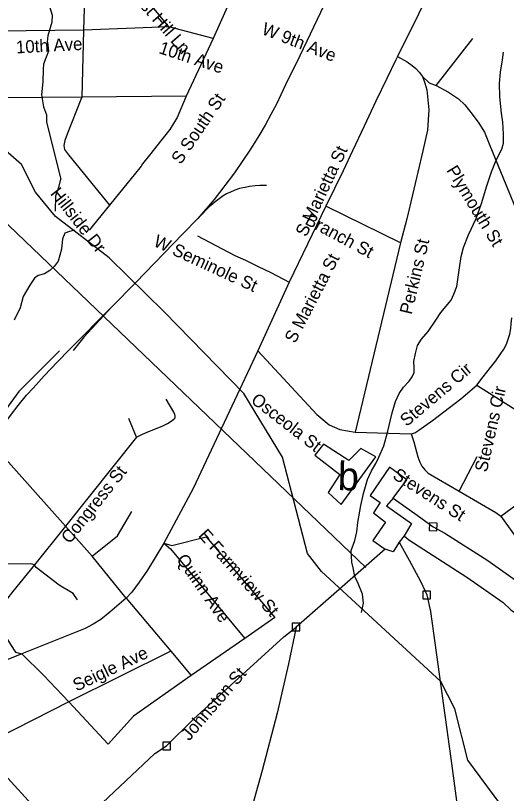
# Model space of a CAD drawing. Extents: x 1268485 to 1426702, y 514839 to 616766.
# Drawn here: x 1346750 to 1349305, y 549246 to 553298 of the extents above; entities that cross this region are included whole.
import ezdxf

# ---------------------------------------------------------------- set-up
doc = ezdxf.new("R2010")
doc.units = 0
for name, color, linetype in [('Old_Level_10', 7, 'Continuous'), ('Old_Level_22', 7, 'Continuous'), ('Old_Level_35', 7, 'Continuous'), ('Old_Level_44', 7, 'Continuous'), ('Old_Level_56', 7, 'Continuous'), ('Old_Level_59', 7, 'Continuous'), ('Old_Level_62', 7, 'Continuous')]:
    doc.layers.add(name, color=color, linetype=linetype)

msp = doc.modelspace()

# ---------------------------------------------------------------- linework, layer by layer
at = {"layer": 'Old_Level_35'}
for p, q in [((1347114.473, 553585.416), (1347104.016, 553222.422)), ((1347916.329, 553491.143), (1347778.534, 553178.797)), ((1347547.953, 553239.185), (1347104.016, 553222.422)), ((1347778.534, 553178.797), (1347547.953, 553239.185)), ((1347104.016, 553222.422), (1346625.116, 553216.68)), ((1347104.016, 553222.422), (1347093.968, 552872.603)), ((1347778.534, 553178.797), (1347637.766, 552877.986)), ((1348939.232, 552934.016), (1349129.828, 553178.9)), ((1347637.766, 552877.986), (1347093.968, 552872.603)), ((1347238.53, 552309.684), (1347132.62, 552180.399)), ((1348365.086, 552305.634), (1348173.772, 551908.961)), ((1348753.044, 552114.73), (1348365.086, 552305.634)), ((1348753.044, 552114.73), (1348517.952, 551127.712)), ((1348173.772, 551908.961), (1348010.756, 551551.914)), ((1349151.666, 551373.211), (1349714.226, 551015.549)), ((1347379.913, 551101.26), (1347339.108, 551198.814)), ((1347009.589, 550637.33), (1346596.512, 551101.363)), ((1347378.99, 551101.927), (1347009.589, 550637.33)), ((1348517.952, 551127.712), (1348809.844, 551118.587)), ((1349275.415, 550690.08), (1349714.226, 551015.549)), ((1349059.597, 550821.211), (1349152.999, 551001.452)), ((1347009.589, 550637.33), (1346847.598, 550436.123)), ((1347147.897, 550481.696), (1347009.589, 550637.33)), ((1347324.857, 550262.29), (1347147.897, 550481.696)), ((1347324.857, 550262.29), (1347557.796, 549987.52)), ((1348099.133, 550163.147), (1347942.474, 550052.266)), ((1347942.474, 550052.266), (1347664.423, 549859.875)), ((1347557.796, 549987.52), (1347027.224, 549722.132)), ((1347557.796, 549987.52), (1347664.423, 549859.875)), ((1347027.224, 549722.132), (1346562.165, 549485.86)), ((1347231.25, 549501.547), (1347027.224, 549722.132)), ((1346562.165, 549485.86), (1347055.008, 548948.931))]:
    msp.add_line(p, q, dxfattribs=at)
for points in [[(1347547.953, 553239.185), (1347271.031, 553581.263), (1347114.473, 553585.416)], [(1348956.046, 553527.078), (1348847.163, 553305.673), (1348738.383, 553084.319)], [(1348738.383, 553084.319), (1348730.284, 553068.018), (1348683.122, 552970.515), (1348626.015, 552851.944), (1348563.884, 552721.634), (1348503.496, 552593.732), (1348454.489, 552488.745), (1348365.086, 552305.634)], [(1348738.383, 553084.319), (1348788.724, 553057.201), (1348814.253, 553038.08), (1348833.425, 553022.138), (1348850.342, 553004.041), (1348868.489, 552981.23)], [(1348868.489, 552981.23), (1348880.279, 552946.832), (1348890.327, 552910.743), (1348900.579, 552806.525), (1348894.223, 552700.923), (1348870.744, 552594.194), (1348843.472, 552482.081), (1348815.483, 552363.51), (1348787.596, 552239.915), (1348753.044, 552114.73)], [(1348868.489, 552981.23), (1348903.04, 552947.755), (1348939.232, 552934.016)], [(1348939.232, 552934.016), (1349002.9, 552899.927), (1349055.906, 552864.913), (1349088.1, 552832.618), (1349127.675, 552784.175), (1349160.791, 552737.576), (1349191.241, 552690.004), (1349218.615, 552621.312), (1349425.205, 552117.14)], [(1347093.968, 552872.603), (1346689.298, 552869.117), (1346664.076, 552870.194), (1346649.108, 552872.705), (1346638.342, 552878.754)], [(1347093.968, 552872.603), (1347088.637, 552861.582), (1347017.996, 552680.828), (1347005.488, 552646.687), (1347001.387, 552620.953), (1347004.77, 552600.14), (1347024.66, 552572.612), (1347238.53, 552309.684)], [(1347637.766, 552877.986), (1347591.014, 552767.976), (1347552.67, 552704.512), (1347504.995, 552644.124), (1347454.757, 552580.301), (1347410.671, 552525.194)], [(1347410.671, 552525.194), (1347403.494, 552513.352), (1347366.79, 552468.805), (1347313.476, 552401.752), (1347238.53, 552309.684)], [(1347696.924, 552151.332), (1347891.211, 552048.243), (1347946.985, 552024.252), (1348013.011, 551991.289), (1348078.116, 551960.275), (1348173.772, 551908.961)], [(1349301.251, 551576.264), (1349306.583, 551591.438), (1349314.887, 551612.558), (1349322.269, 551638.087), (1349327.6, 551668.024), (1349330.676, 551692.99), (1349333.137, 551724.363)], [(1349151.666, 551373.211), (1349184.987, 551415.4), (1349222.204, 551464.459), (1349249.27, 551499.267), (1349273.262, 551532.127), (1349290.896, 551560.577), (1349301.251, 551576.264)], [(1346977.909, 551550.991), (1346765.987, 551339.583), (1346711.238, 551262.791), (1346596.512, 551101.363)], [(1348010.756, 551551.914), (1347673.548, 550834.129), (1347521.502, 550549.517)], [(1348010.756, 551551.914), (1348318.744, 551219.422), (1348382.72, 551166.877), (1348438.392, 551141.81), (1348517.952, 551127.712)], [(1348809.844, 551118.587), (1348827.786, 551124.073), (1348844.6, 551135.504), (1348921.085, 551189.074), (1349067.082, 551301.956), (1349151.666, 551373.211)], [(1347379.913, 551101.26), (1347410.979, 551117.101), (1347447.785, 551132.378), (1347512.377, 551159.29), (1347540.469, 551173.491), (1347564.46, 551188.92), (1347576.148, 551197.327), (1347580.147, 551202.761), (1347580.659, 551206.914), (1347580.659, 551210.707), (1347579.634, 551219.627), (1347574.405, 551232.084), (1347533.907, 551299.443)], [(1348809.844, 551118.587), (1348823.582, 551077.372), (1348843.267, 550999.606), (1348853.725, 550972.18), (1348865.208, 550951.572), (1348880.279, 550931.939), (1348898.426, 550913.638), (1349059.597, 550821.211)], [(1349059.597, 550821.211), (1349250.398, 550710.073), (1349275.415, 550690.08)], [(1347147.897, 550481.696), (1347279.745, 550587.862), (1347355.615, 550714.43)], [(1349275.415, 550690.08), (1349483.235, 550401.213), (1349557.156, 550332.11), (1349627.489, 550291.612), (1349677.624, 550265.776)], [(1347521.502, 550549.517), (1347562.922, 550537.265), (1347742.65, 550581.915), (1348099.133, 550163.147)], [(1347521.502, 550549.517), (1347437.225, 550409.415), (1347393.139, 550346.874), (1347354.384, 550294.125), (1347324.857, 550262.29)], [(1347521.502, 550549.517), (1347555.848, 550519.835), (1347942.474, 550052.266)], [(1346847.598, 550436.123), (1346829.963, 550441.916), (1346447.029, 550438.379), (1346386.231, 550438.635), (1346358.036, 550437.302), (1346339.581, 550436.328), (1346321.639, 550432.637), (1346304.005, 550426.947), (1346283.91, 550418.232)], [(1346847.598, 550436.123), (1346733.897, 550296.636), (1346704.369, 550257.676), (1346690.426, 550229.738), (1346678.533, 550187.087)], [(1347071.72, 550255.062), (1347049.164, 550286.948), (1346977.088, 550331.187), (1346856.415, 550422.641), (1346847.598, 550436.123)], [(1347324.857, 550262.29), (1347241.093, 550190.317), (1347193.111, 550152.382), (1347153.536, 550128.391), (1347111.603, 550105.477), (1346782.391, 549973.269)], [(1346678.533, 550187.087), (1346676.79, 550168.684), (1346678.533, 550151.254), (1346683.044, 550123.111), (1346689.708, 550096.762), (1346697.602, 550070.31), (1346707.137, 550047.857), (1346722.926, 550022.021), (1346749.275, 549982.138), (1346782.391, 549973.269)], [(1346782.391, 549973.269), (1346550.888, 549881.816), (1346491.217, 549852.698), (1346439.544, 549817.789), (1346344.503, 549735.819)], [(1347027.224, 549722.132), (1346895.58, 549862.438), (1346782.391, 549973.269)], [(1347664.423, 549859.875), (1347362.996, 549648.979), (1347231.25, 549501.547)]]:
    msp.add_lwpolyline(points, dxfattribs=at)
at = {"layer": 'Old_Level_44'}
for points in [[(1348444.749, 553541.38), (1348229.239, 553088.83), (1348155.83, 552937.707), (1348131.224, 552885.521), (1348107.335, 552837.078), (1348079.038, 552783.2), (1348048.485, 552727.273), (1348021.419, 552680.059), (1348002.246, 552649.199), (1347969.951, 552597.013), (1347890.288, 552479.672), (1347783.046, 552340.237), (1347697.846, 552240.889)], [(1347697.846, 552240.889), (1347765.001, 552308.505), (1347789.3, 552329.369), (1347808.882, 552344.44), (1347831.335, 552360.69), (1347848.457, 552370.687), (1347867.425, 552379.043), (1347893.261, 552389.962), (1347917.457, 552398.677), (1347932.529, 552402.88), (1347945.857, 552404.931), (1347967.49, 552409.544), (1347996.71, 552413.338), (1348022.239, 552415.388), (1348041.411, 552414.927), (1348055.97, 552415.388)], [(1347251.551, 551781.213), (1347375.094, 551908.243), (1347620.952, 552161.124), (1347697.846, 552240.889)], [(1345456.73, 549157.674), (1345521.834, 549285.422), (1345542.339, 549321.768), (1345574.019, 549373.492), (1345788.299, 549725.053), (1345901.385, 549906.679), (1345943.523, 549975.935), (1345968.642, 550014.382), (1346066.247, 550172.99), (1346066.76, 550172.99), (1346186.51, 550370.507), (1346285.55, 550530.395), (1346354.345, 550639.381), (1346410.222, 550730.373), (1346617.324, 551065.171), (1346675.354, 551147.859), (1346722.619, 551213.834), (1346763.527, 551266.892), (1346806.895, 551319.898), (1346840.729, 551357.422), (1346897.836, 551421.296), (1346968.476, 551494.397), (1347031.12, 551558.271), (1347251.551, 551781.213)], [(1347251.551, 551781.213), (1347105.041, 551623.375), (1347050.292, 551552.837)]]:
    msp.add_lwpolyline(points, dxfattribs=at)
at = {"layer": 'Old_Level_56'}
for p, q in [((1348772.91, 550588.239), (1348746.228, 550554.96)), ((1348673.258, 550518.411), (1348210.069, 550112.54))]:
    msp.add_line(p, q, dxfattribs=at)
for points in [[(1343197.859, 555401.572), (1343694.839, 555209.776), (1344145.672, 555017.979), (1344450.24, 554823.724), (1344690.819, 554583.044), (1345107.207, 554064.657), (1346134.297, 552759.432), (1348573.366, 550422.633)], [(1348437.788, 550907.937), (1348377.651, 550813.102), (1348444.243, 550751.533), (1348625.926, 550999.795), (1348546.771, 551043.609), (1348485.478, 550980.813), (1348353.125, 551065.718), (1348307.958, 551008.799), (1348437.788, 550907.937)], [(1348715.218, 550783.694), (1348787.392, 550880.087), (1348696.68, 550946.145), (1348595.455, 550798.312), (1348648.734, 550761.222), (1348613.444, 550707.907), (1348676.477, 550658.414), (1348610.344, 550563.899), (1348673.258, 550518.411)], [(1348715.218, 550783.694), (1348680.21, 550744.38), (1348810.402, 550651.515), (1348772.91, 550588.239)], [(1348715.218, 550783.694), (1348841.29, 550694.914), (1348923.923, 550635.022), (1348985.278, 550601.571), (1349208.305, 550458.613), (1349501.844, 550250.005), (1349710.669, 550097.329), (1349779.667, 550055.92), (1349846.701, 550006.347), (1350228.917, 549739.926), (1350396.384, 549620.098), (1350466.625, 549630.489), (1350749.199, 549642.408), (1351099.809, 549664.561), (1351462.505, 549690.673), (1351602.671, 549695.654), (1351688.956, 549707.723), (1352168.455, 549761.097), (1352345.067, 549787.355), (1352419.269, 549795.665), (1352503.472, 549803.774), (1352798.485, 549837.252)], [(1348903.519, 550615.423), (1348943.521, 550614.618), (1348944.327, 550654.62), (1348904.325, 550655.426), (1348903.519, 550615.423)], [(1348772.91, 550588.239), (1348796.509, 550567.754), (1349098.33, 550372.986), (1349287.556, 550240.714), (1349328.594, 550201.869), (1349391.707, 550156.377), (1349673.41, 549956.211), (1349833.158, 549850.545), (1349922.152, 549798.529), (1350149.301, 549661.491), (1350374.168, 549520.498), (1350619.155, 549375.097), (1350686.39, 549335.525), (1350853.106, 549277.741), (1351391.859, 549113.819), (1351669.977, 549023.779), (1351709.613, 549004.772), (1351832.732, 548968.076), (1351906.334, 548946.584), (1352075.208, 548886.756), (1352291.725, 548817.966), (1352540.164, 548744.53), (1352706.997, 548682.743), (1352786.516, 548656.93)], [(1348746.228, 550554.96), (1348714.979, 550503.565), (1348673.258, 550518.411)], [(1348746.228, 550554.96), (1348798.174, 550461.67), (1348859.722, 550348.377), (1348890.15, 550279.532), (1348910.22, 550193.086), (1349015.475, 549428.401), (1349139.19, 548507.27)], [(1348869.746, 550259.933), (1348909.749, 550259.127), (1348910.555, 550299.13), (1348870.552, 550299.936), (1348869.746, 550259.933)], [(1348189.665, 550092.941), (1348229.668, 550092.136), (1348230.473, 550132.139), (1348190.47, 550132.945), (1348189.665, 550092.941)], [(1348210.069, 550112.54), (1348169.999, 549921.255), (1348112.199, 549664.296), (1348033.556, 549365.936), (1347887.957, 548842.815), (1347749.887, 548385.575), (1347623.903, 547932.294), (1347430.598, 547246.056), (1346822.557, 545072.451), (1346515.911, 543964.491), (1346252.969, 543019.729), (1346237.442, 542944.205), (1346202.784, 542832.849), (1345973.91, 542069.489), (1345771.12, 541309.605), (1345580.378, 540641.322), (1345430.703, 540114.481), (1345418.971, 540038.681), (1345218.351, 539376.601), (1345013.922, 538634.757), (1345006.474, 538572.878)], [(1347172.783, 549168.767), (1347475.271, 549454.215), (1347536.08, 549493.01), (1347675.342, 549631.873), (1348147.018, 550061.785), (1348210.069, 550112.54)], [(1347515.677, 549473.411), (1347555.679, 549472.606), (1347556.484, 549512.608), (1347516.482, 549513.413), (1347515.677, 549473.411)]]:
    msp.add_lwpolyline(points, dxfattribs=at)
at = {"layer": 'Old_Level_59'}
msp.add_lwpolyline([(1349266.905, 549198.89), (1349104.914, 549418.757), (1349035.914, 549686.043), (1348963.941, 549828.605), (1348342.94, 550402.443), (1348269.942, 550495.844), (1348139.939, 550997.402), (1347938.885, 551329.689), (1347522.937, 551754.967), (1347236.889, 552036.401), (1346957.916, 552252.115), (1346852.929, 552378.992), (1346780.854, 552521.554), (1346598.582, 552680.216), (1346333.938, 552773.194), (1346170.304, 552841.916), (1346117.778, 552872.235), (1346002.628, 552837.874), (1345913.74, 552831.81), (1345855.155, 552850.001), (1345820.812, 552926.808), (1345802.261, 553070.997)], dxfattribs=at)
at = {"layer": 'Old_Level_62'}
msp.add_line((1346911.369, 552742.907), (1346984.778, 552445.224), dxfattribs=at)
for points in [[(1346916.495, 553160.496), (1346919.264, 553194.022), (1346940.897, 553265.739), (1346941.614, 553297.933), (1346930.542, 553338.43)], [(1346916.495, 553160.496), (1346921.519, 553112.821), (1346908.703, 553081.09), (1346895.888, 553045.206), (1346893.427, 553017.37), (1346891.889, 552953.393), (1346884.405, 552885.419), (1346895.17, 552822.878), (1346910.139, 552780.689), (1346911.369, 552742.907)], [(1348549.94, 550188.984), (1348561.013, 550237.223), (1348556.092, 550283.257), (1348533.331, 550339.492), (1348516.107, 550375.991), (1348506.982, 550420.488), (1348499.6, 550450.989), (1348497.037, 550510.916), (1348516.209, 550563.871), (1348527.18, 550607.957), (1348532.306, 550657.938), (1348548.095, 550745.444), (1348561.628, 550809.164), (1348581.211, 550880.984), (1348602.229, 550926.505), (1348625.092, 550963.773), (1348641.701, 550997.914), (1348667.128, 551057.329), (1348686.71, 551126.687), (1348710.906, 551228.752), (1348728.233, 551288.32), (1348747.2, 551329.791), (1348769.961, 551362.959), (1348798.566, 551392.742), (1348815.073, 551416.22), (1348825.633, 551438.161), (1348824.198, 551463.639), (1348822.865, 551495.678), (1348831.784, 551538.176), (1348842.755, 551579.801), (1348863.465, 551613.02), (1348898.324, 551652.543), (1348937.694, 551711.65), (1348964.556, 551751.327), (1349018.074, 551815.867), (1349030.685, 551846.01), (1349047.602, 551887.533), (1349061.75, 551984.882), (1349069.03, 552043.014), (1349082.051, 552090.329), (1349107.58, 552156.305), (1349147.462, 552241.658), (1349177.195, 552324.755), (1349200.981, 552406.314), (1349226.817, 552483.773), (1349252.141, 552544.827), (1349281.361, 552602.498), (1349290.178, 552634.332), (1349289.153, 552680.264), (1349286.59, 552742.702), (1349279.516, 552790.429), (1349271.416, 552875.115), (1349268.955, 552944.935), (1349274.287, 553003.068), (1349285.667, 553066.839), (1349290.588, 553108.413)], [(1346957.096, 552279.182), (1346958.941, 552359.563), (1346976.063, 552409.288), (1346984.778, 552445.224)], [(1347056.956, 552179.527), (1347030.812, 552173.478), (1347006.616, 552164.097), (1346994.005, 552134.826), (1346988.776, 552080.794), (1346971.449, 552018.766), (1346950.842, 551991.289), (1346928.286, 551970.374), (1346899.989, 551952.893), (1346867.693, 551943.717), (1346847.393, 551929.363), (1346824.632, 551894.504), (1346789.261, 551835.296), (1346773.882, 551774.908), (1346742.509, 551711.547)]]:
    msp.add_lwpolyline(points, dxfattribs=at)

# ---------------------------------------------------------------- texts
at = {"layer": 'Old_Level_10'}
for s, height, rotation, p in [('Forest Hill Ln', 65.61666, 311.0858, (1347276.808, 553481.674)), ('W 9th Ave', 65.6167, 338.651133, (1348026.388, 553203.427)), ('10th Ave', 65.6167, 3.094206, (1346753.433, 553100.817)), ('10th Ave', 65.6167, 341.789494, (1347491.394, 553103.536)), ('S South St', 65.6167, 55.821592, (1347609.346, 552518.504)), ('S Marietta St', 65.61666, 64.633575, (1348263.016, 552141.447)), ('Plymouth St', 65.61666, 301.444792, (1348990.68, 552492.344)), ('Hillside Dr', 65.61666, 308.100844, (1346927.572, 552370.065)), ('Branch St', 65.6167, 331.813594, (1348251.597, 552214.832)), ('W Seminole St', 65.61666, 335.213225, (1347462.867, 552099.813)), ('Perkins St', 65.6167, 76.643919, (1348811.934, 551737.444)), ('S Marietta St', 65.61666, 62.532867, (1348204.734, 551586.433)), ('Stevens Cir', 65.61665, 40.264303, (1348785.802, 551153.923)), ('Stevens Cir', 65.61666, 77.151428, (1349203.187, 550916.303)), ('Osceola St', 65.6167, 322.148683, (1347970.383, 551285.457)), ('Congress St', 65.61666, 51.602472, (1347032.215, 550542.343)), ('Stevens St', 65.6167, 327.380008, (1348707.847, 550890.123)), ('E Farmview St', 65.61666, 311.802283, (1347697.989, 550587.471)), ('Quinn Ave', 65.6167, 304.768969, (1347584.205, 550464.893)), ('Seigle Ave', 65.6167, 25.390503, (1347067.012, 549775.836)), ('Johnston St', 65.61666, 49.374328, (1347653.865, 549516.103))]:
    msp.add_text(s, height=height, rotation=rotation, dxfattribs=at).set_placement(p)
at = {"layer": 'Old_Level_22'}
msp.add_text('b', height=147.638, rotation=358.314892, dxfattribs=at).set_placement((1348425.578, 550826.318))

doc.saveas('drawing.dxf')
